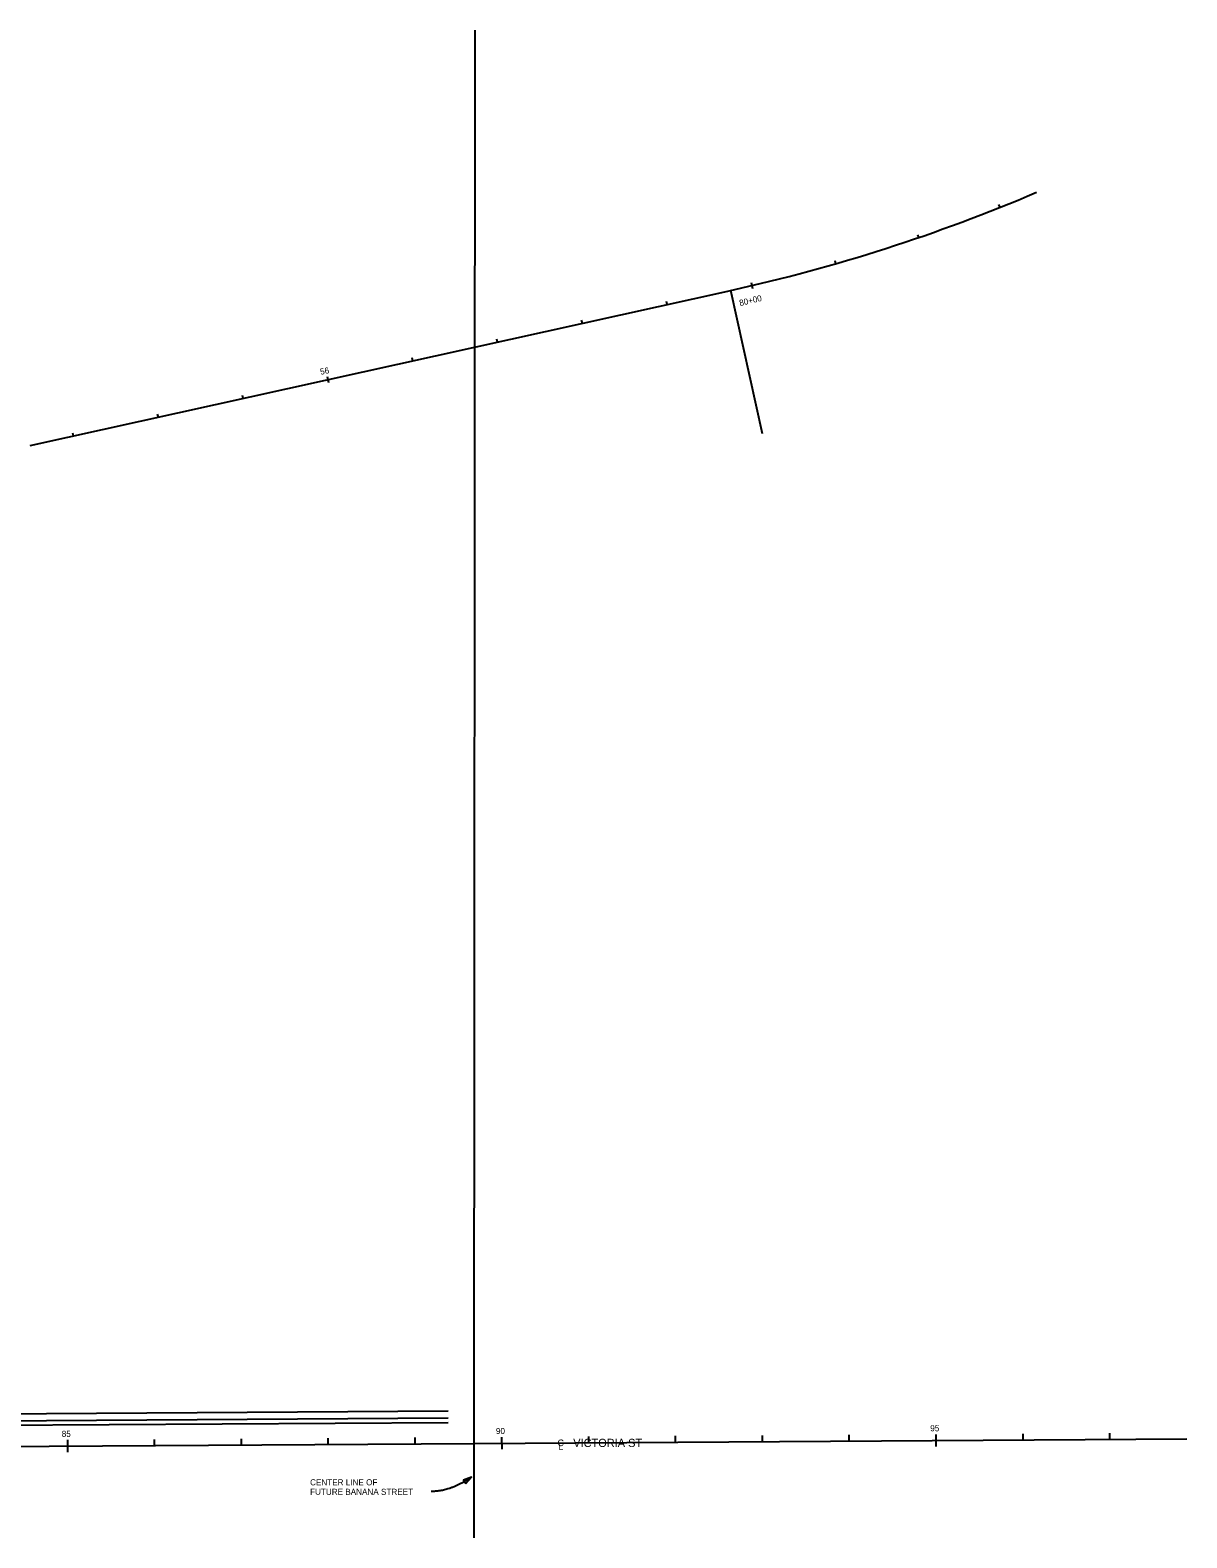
# Model space of a CAD drawing. Extents: x 6711323 to 6714641, y 1869258 to 1871224.
# Drawn here: x 6713309 to 6714641, y 1869488 to 1871224 of the extents above; entities that cross this region are included whole.
import ezdxf

# ---------------------------------------------------------------- set-up
doc = ezdxf.new("R2010")
doc.units = 0
for name, color, linetype in [('Contours (7)', 7, 'Continuous'), ('Level 13', 7, 'Continuous'), ('Level 14', 7, 'Continuous'), ('Level 16', 7, 'Continuous'), ('Level 46', 7, 'Continuous'), ('Level 59', 7, 'Continuous'), ('Level 7', 7, 'Continuous'), ('Main Anno (16)', 7, 'Continuous')]:
    doc.layers.add(name, color=color, linetype=linetype)

msp = doc.modelspace()

# ---------------------------------------------------------------- linework, layer by layer
at = {"layer": 'Contours (7)'}
msp.add_line((6713820.1, 1869487.8), (6713820.2, 1869596.7), dxfattribs=at)
at = {"layer": 'Level 13'}
for p, q in [((6713820.2, 1869596.6), (6713821.4, 1871224.2)), ((6713309, 1870745.7), (6714115.6, 1870924.4)), ((6713820.2, 1869596.6), (6714640.8, 1869601.9)), ((6712709.1, 1869589.4), (6713820.2, 1869596.6))]:
    msp.add_line(p, q, dxfattribs=at)
msp.add_arc((6713683, 1872877.1), 2000, 282.4898, 293.1044, dxfattribs=at)
at = {"layer": 'Level 14'}
for p, q in [((6714425.8, 1871020.1), (6714424.5, 1871023.4)), ((6714332.1, 1870985.3), (6714331, 1870988.6)), ((6714236.7, 1870955.2), (6714235.8, 1870958.6)), ((6714152.1, 1870759.4), (6714115.6, 1870924.4)), ((6714139.2, 1870933.4), (6714140.8, 1870926.6)), ((6714042.4, 1870908.2), (6714041.6, 1870911.6)), ((6713944.8, 1870886.6), (6713944, 1870890)), ((6713847.1, 1870864.9), (6713846.4, 1870868.4)), ((6713749.5, 1870843.3), (6713748.7, 1870846.7)), ((6713651.1, 1870825.1), (6713652.6, 1870818.3)), ((6713554.2, 1870800.1), (6713553.5, 1870803.5)), ((6713456.6, 1870778.4), (6713455.8, 1870781.9)), ((6713359, 1870756.8), (6713358.2, 1870760.2))]:
    msp.add_line(p, q, dxfattribs=at)
for points in [[(6713351.8, 1869600.6), (6713351.9, 1869586.6)], [(6713451.8, 1869601.2), (6713451.8, 1869594.2)], [(6713551.8, 1869601.9), (6713551.8, 1869594.9)], [(6713651.8, 1869602.5), (6713651.8, 1869595.5)], [(6713751.8, 1869603.2), (6713751.8, 1869596.2)], [(6713851.8, 1869603.8), (6713851.9, 1869589.8)], [(6713951.8, 1869604.5), (6713951.8, 1869597.5)], [(6714051.8, 1869605.1), (6714051.8, 1869598.1)], [(6714151.8, 1869605.8), (6714151.8, 1869598.8)], [(6714251.8, 1869606.4), (6714251.8, 1869599.4)], [(6714351.8, 1869607), (6714351.9, 1869593)], [(6714451.8, 1869607.7), (6714451.8, 1869600.7)], [(6714551.8, 1869608.3), (6714551.8, 1869601.3)]]:
    msp.add_lwpolyline(points, dxfattribs=at)
at = {"layer": 'Level 16'}
msp.add_lwpolyline([(6713810.8, 1869550.3), (6713817.1, 1869557.8), (6713808, 1869554.2)], close=True, dxfattribs=at)
msp.add_open_spline([(6713817.1, 1869557.8), (6713793.8, 1869541.2), (6713770.6, 1869541.2)], degree=2, dxfattribs=at)
at = {"layer": 'Level 46'}
for p, q in [((6713202.6, 1869617.1), (6713790.4, 1869620.8)), ((6713204.7, 1869622.3), (6713790.2, 1869626)), ((6713206.3, 1869630.3), (6713790.2, 1869634))]:
    msp.add_line(p, q, dxfattribs=at)
at = {"layer": 'Level 7'}
msp.add_line((6713820.1, 1869487.8), (6713820.2, 1869596.7), dxfattribs=at)
at = {"layer": 'Main Anno (16)'}
msp.add_lwpolyline([(6713810.8, 1869550.3), (6713817.1, 1869557.8), (6713808, 1869554.2)], close=True, dxfattribs=at)
msp.add_lwpolyline([(6713810.8, 1869550.3), (6713817.1, 1869557.8), (6713808, 1869554.2)], close=True, dxfattribs=at)
msp.add_open_spline([(6713817.1, 1869557.8), (6713793.8, 1869541.2), (6713770.6, 1869541.2)], degree=2, dxfattribs=at)
msp.add_open_spline([(6713817.1, 1869557.8), (6713793.8, 1869541.2), (6713770.6, 1869541.2)], degree=2, dxfattribs=at)

# ---------------------------------------------------------------- texts
at = {"layer": 'Level 14'}
for s, rotation, p in [('80+00', 13.2076, (6714126.4, 1870906.4)), ('95', 0.3697, (6714345.4, 1869610.5)), ('85', 0.3699, (6713345.4, 1869604)), ('90', 0.3697, (6713845.3, 1869607.3))]:
    msp.add_text(s, height=7, rotation=rotation, dxfattribs=at).set_placement(p)
at = {"layer": 'Level 16'}
msp.add_text('56', height=7, rotation=11.4041, dxfattribs=at).set_placement((6713643.6, 1870827.2))
for s, p in [('CENTER LINE OF ', (6713631.3, 1869548.3)), ('FUTURE BANANA STREET', (6713631.3, 1869537.3))]:
    msp.add_text(s, height=7, dxfattribs=at).set_placement(p)
at = {"layer": 'Level 59'}
for s, height, p in [('C', 7.62, (6713916.2, 1869593.4)), ('VICTORIA ST', 9.449, (6713934.3, 1869592.4)), ('L', 7.62, (6713917, 1869589.4))]:
    msp.add_text(s, height=height, dxfattribs=at).set_placement(p)
at = {"layer": 'Main Anno (16)'}
for s, p in [('CENTER LINE OF ', (6713631.3, 1869548.3)), ('FUTURE BANANA STREET', (6713631.3, 1869537.3))]:
    msp.add_text(s, height=7, dxfattribs=at).set_placement(p)

doc.saveas('drawing.dxf')
